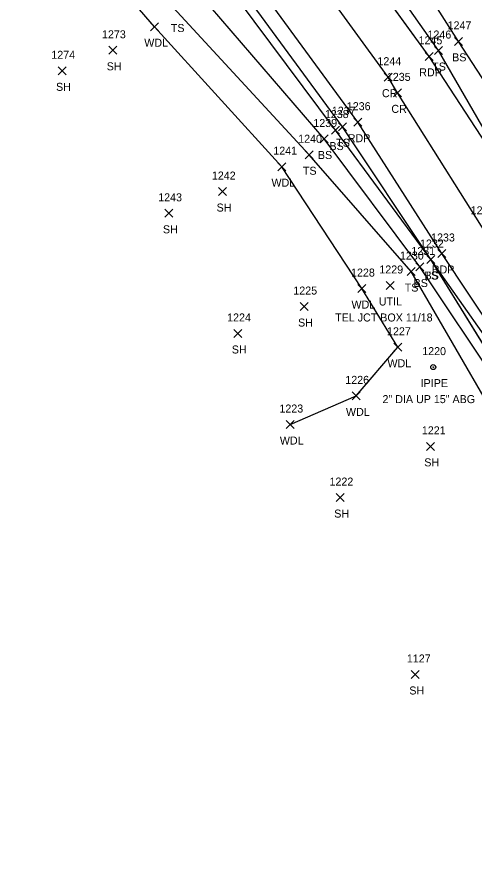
# Model space of a CAD drawing. Extents: x 1415642 to 1422021, y 544543 to 547232.
# Drawn here: x 1416332.5 to 1416447, y 546334.5 to 546547.3 of the extents above; entities that cross this region are included whole.
import ezdxf

# ---------------------------------------------------------------- set-up
doc = ezdxf.new("R2010")
doc.units = 0
for name, color, linetype in [('L_A', 7, 'Continuous'), ('L_I', 7, 'Continuous'), ('L_TIC', 7, 'Continuous'), ('LAWA', 7, 'Continuous'), ('LELB', 7, 'Continuous'), ('M_A', 7, 'Continuous'), ('M_C', 7, 'Continuous'), ('M_I', 7, 'Continuous'), ('MPIP', 7, 'Continuous'), ('P_A', 7, 'Continuous'), ('P_I', 7, 'Continuous'), ('P_TIC', 7, 'Continuous'), ('PET', 7, 'Continuous'), ('PRC', 7, 'Continuous'), ('U_A', 7, 'Continuous'), ('U_C', 7, 'Continuous'), ('U_I', 7, 'Continuous'), ('UDEFAULT', 7, 'Continuous')]:
    doc.layers.add(name, color=color, linetype=linetype)

msp = doc.modelspace()

# ---------------------------------------------------------------- linework, layer by layer
at = {"layer": 'L_TIC'}
for points in [[(1416365.86, 546543.85), (1416367.86, 546545.85)], [(1416367.86, 546543.85), (1416365.86, 546545.85)], [(1416441.83, 546540.19), (1416443.83, 546542.19)], [(1416443.83, 546540.19), (1416441.83, 546542.19)], [(1416355.4, 546537.95), (1416357.4, 546539.95)], [(1416357.4, 546537.95), (1416355.4, 546539.95)], [(1416436.87, 546537.89), (1416438.87, 546539.89)], [(1416438.87, 546537.89), (1416436.87, 546539.89)], [(1416342.74, 546532.82), (1416344.74, 546534.82)], [(1416344.74, 546532.82), (1416342.74, 546534.82)], [(1416412.88, 546518.84), (1416414.88, 546520.84)], [(1416414.88, 546518.84), (1416412.88, 546520.84)], [(1416411.14, 546518.01), (1416413.14, 546520.01)], [(1416413.14, 546518.01), (1416411.14, 546520.01)], [(1416408.26, 546515.78), (1416410.26, 546517.78)], [(1416410.26, 546515.78), (1416408.26, 546517.78)], [(1416404.55, 546511.84), (1416406.55, 546513.84)], [(1416406.55, 546511.84), (1416404.55, 546513.84)], [(1416397.67, 546508.86), (1416399.67, 546510.86)], [(1416399.67, 546508.86), (1416397.67, 546510.86)], [(1416382.88, 546502.64), (1416384.88, 546504.64)], [(1416384.88, 546502.64), (1416382.88, 546504.64)], [(1416369.46, 546497.2), (1416371.46, 546499.2)], [(1416371.46, 546497.2), (1416369.46, 546499.2)], [(1416434.93, 546485.65), (1416436.93, 546487.65)], [(1416436.93, 546485.65), (1416434.93, 546487.65)], [(1416434.93, 546485.65), (1416436.93, 546487.65)], [(1416436.93, 546485.65), (1416434.93, 546487.65)], [(1416430.01, 546482.64), (1416432.01, 546484.64)], [(1416432.01, 546482.64), (1416430.01, 546484.64)], [(1416432.2, 546483.78), (1416434.2, 546485.78)], [(1416434.2, 546483.78), (1416432.2, 546485.78)], [(1416417.68, 546478.39), (1416419.68, 546480.39)], [(1416419.68, 546478.39), (1416417.68, 546480.39)], [(1416403.25, 546473.89), (1416405.25, 546475.89)], [(1416405.25, 546473.89), (1416403.25, 546475.89)], [(1416386.69, 546467.16), (1416388.69, 546469.16)], [(1416388.69, 546467.16), (1416386.69, 546469.16)], [(1416426.69, 546463.71), (1416428.69, 546465.71)], [(1416428.69, 546463.71), (1416426.69, 546465.71)], [(1416416.31, 546451.56), (1416418.31, 546453.56)], [(1416418.31, 546451.56), (1416416.31, 546453.56)], [(1416399.77, 546444.4), (1416401.77, 546446.4)], [(1416401.77, 546444.4), (1416399.77, 546446.4)], [(1416434.83, 546438.94), (1416436.83, 546440.94)], [(1416436.83, 546438.94), (1416434.83, 546440.94)], [(1416412.3, 546426.14), (1416414.3, 546428.14)], [(1416414.3, 546426.14), (1416412.3, 546428.14)], [(1416431.07, 546381.91), (1416433.07, 546383.91)], [(1416433.07, 546381.91), (1416431.07, 546383.91)]]:
    msp.add_lwpolyline(points, dxfattribs=at)
at = {"layer": 'LAWA'}
for points in [[(1416400.77, 546445.4), (1416417.31, 546452.56), (1416427.69, 546464.71), (1416418.68, 546479.39), (1416398.67, 546509.86), (1416366.86, 546544.85), (1416337.81, 546578.41)], [(1416400.78, 546445.41), (1416417.3, 546452.56), (1416427.69, 546464.71), (1416418.68, 546479.4), (1416398.68, 546509.86), (1416366.86, 546544.85), (1416337.81, 546578.41)]]:
    msp.add_lwpolyline(points, dxfattribs=at)
at = {"layer": 'LELB'}
for points in [[(1416487.57, 546505.93), (1416480.71, 546505.12), (1416469.86, 546502.72), (1416462.76, 546510.55), (1416442.83, 546541.19), (1416430.44, 546560.72), (1416424.35, 546585.18), (1416398.34, 546624.28), (1416389.66, 546643.26), (1416377.3, 546653.03), (1416344.54, 546704.05), (1416343.42, 546724.77), (1416329.35, 546768.04), (1416303.68, 546799.52), (1416274.8, 546819.39), (1416239.26, 546839.41), (1416210.61, 546845.46), (1416203.47, 546849.21), (1416195, 546854.49)], [(1416487.57, 546505.93), (1416480.71, 546505.12), (1416469.86, 546502.72), (1416462.76, 546510.55), (1416442.83, 546541.19), (1416430.44, 546560.72), (1416424.35, 546585.18), (1416398.34, 546624.28), (1416389.66, 546643.27), (1416377.3, 546653.03), (1416344.54, 546704.05), (1416343.42, 546724.76), (1416329.35, 546768.04), (1416303.68, 546799.52), (1416274.8, 546819.4), (1416239.26, 546839.41), (1416210.61, 546845.46), (1416203.48, 546849.21), (1416195, 546854.49)], [(1416462.64, 546496.11), (1416437.87, 546538.89), (1416411.19, 546576.82), (1416382.17, 546614.17), (1416360.8, 546639.39), (1416323.65, 546683.15), (1416301.53, 546707.03), (1416273.6, 546735.69), (1416258.67, 546751.22), (1416224.41, 546784.74), (1416201.13, 546806.07), (1416169.09, 546832.26)], [(1416462.64, 546496.11), (1416437.87, 546538.89), (1416411.18, 546576.82), (1416382.17, 546614.17), (1416360.8, 546639.39), (1416323.65, 546683.15), (1416301.53, 546707.03), (1416273.6, 546735.69), (1416258.67, 546751.22), (1416224.4, 546784.74), (1416201.13, 546806.07), (1416169.09, 546832.26)], [(1416578, 546177.77), (1416578.55, 546199.27), (1416573.9, 546214.14), (1416552.43, 546269), (1416536.22, 546304.5), (1416520.22, 546335.71), (1416500.65, 546371.21), (1416484.25, 546405.14), (1416455.06, 546455.78), (1416435.93, 546486.65), (1416412.14, 546519.01), (1416383.64, 546557.13), (1416352.74, 546592.54), (1416331.82, 546618.14), (1416293.94, 546655.61), (1416274.22, 546680.91), (1416245.72, 546708.98), (1416224.27, 546729.93), (1416198.14, 546753.3), (1416170.94, 546765.48), (1416158.5, 546767.31), (1416141.08, 546772.75), (1416136.01, 546776.95), (1416129, 546780.64)], [(1416578, 546177.77), (1416578.55, 546199.27), (1416573.9, 546214.14), (1416552.42, 546269.01), (1416536.22, 546304.5), (1416520.22, 546335.71), (1416500.65, 546371.22), (1416484.25, 546405.15), (1416455.06, 546455.79), (1416435.93, 546486.65), (1416412.14, 546519.01), (1416383.65, 546557.13), (1416352.74, 546592.54), (1416331.82, 546618.14), (1416293.94, 546655.62), (1416274.22, 546680.91), (1416245.72, 546708.98), (1416224.27, 546729.93), (1416198.14, 546753.3), (1416170.94, 546765.48), (1416158.51, 546767.31), (1416141.09, 546772.75), (1416136.01, 546776.96), (1416129.01, 546780.64)], [(1416503.76, 546247.98), (1416498.74, 546274.69), (1416501.23, 546308.66), (1416502.98, 546324.04), (1416489.47, 546365.32), (1416480.57, 546403.46), (1416453.11, 546455.02), (1416433.2, 546484.78), (1416409.26, 546516.78), (1416378.25, 546552.92), (1416343.61, 546583.91), (1416327.57, 546614.09), (1416289.4, 546651.59), (1416267.58, 546675.69), (1416237.14, 546697.31), (1416220.66, 546725.9), (1416195.41, 546750.9), (1416170.78, 546763.33), (1416158.82, 546764.49), (1416140.16, 546770.72), (1416135.4, 546775.05), (1416128.27, 546778.63)], [(1416503.76, 546247.98), (1416498.74, 546274.69), (1416501.24, 546308.65), (1416502.98, 546324.03), (1416489.47, 546365.32), (1416480.57, 546403.46), (1416453.11, 546455.02), (1416433.2, 546484.78), (1416409.26, 546516.79), (1416378.25, 546552.92), (1416343.61, 546583.91), (1416327.58, 546614.09), (1416289.4, 546651.59), (1416267.58, 546675.69), (1416237.14, 546697.31), (1416220.66, 546725.9), (1416195.42, 546750.9), (1416170.78, 546763.33), (1416158.81, 546764.5), (1416140.16, 546770.72), (1416135.4, 546775.05), (1416128.28, 546778.62)], [(1416480.57, 546403.46), (1416449.3, 546452.17), (1416431.01, 546483.64), (1416405.55, 546512.84), (1416372.51, 546548.53), (1416341.49, 546581.99), (1416324.84, 546612.16), (1416286, 546648.13), (1416263.12, 546671.71)], [(1416480.57, 546403.46), (1416449.3, 546452.17), (1416431.01, 546483.64), (1416405.56, 546512.84), (1416372.51, 546548.53), (1416341.49, 546581.99), (1416324.84, 546612.16), (1416286, 546648.13), (1416263.12, 546671.71)], [(1416587.9, 546190.79), (1416583.62, 546199.97), (1416577.46, 546215.02), (1416552.43, 546269), (1416533.39, 546301.47), (1416525.26, 546316.84), (1416520.22, 546335.71), (1416504.13, 546372.91), (1416486.87, 546406.07), (1416456.87, 546456.96), (1416435.93, 546486.65), (1416413.88, 546519.84), (1416385.73, 546558.12)], [(1416587.91, 546190.79), (1416583.61, 546199.97), (1416577.46, 546215.02), (1416552.42, 546269.01), (1416533.39, 546301.47), (1416525.26, 546316.84), (1416520.22, 546335.71), (1416504.13, 546372.91), (1416486.87, 546406.07), (1416456.87, 546456.96), (1416435.93, 546486.65), (1416413.88, 546519.84), (1416385.73, 546558.12)]]:
    msp.add_lwpolyline(points, dxfattribs=at)
at = {"layer": 'MPIP'}
for radius in [0.625, 0.0833]:
    msp.add_circle((1416436.56, 546459.75), radius, dxfattribs=at)
at = {"layer": 'P_TIC'}
for points in [[(1416434.56, 546536.44), (1416436.56, 546538.44)], [(1416436.56, 546536.44), (1416434.56, 546538.44)], [(1416424.29, 546531.23), (1416426.29, 546533.23)], [(1416426.29, 546531.23), (1416424.29, 546533.23)], [(1416426.64, 546527.31), (1416428.64, 546529.31)], [(1416428.64, 546527.31), (1416426.64, 546529.31)], [(1416416.68, 546519.98), (1416418.68, 546521.98)], [(1416418.68, 546519.98), (1416416.68, 546521.98)], [(1416437.7, 546487.16), (1416439.7, 546489.16)], [(1416439.7, 546487.16), (1416437.7, 546489.16)]]:
    msp.add_lwpolyline(points, dxfattribs=at)
at = {"layer": 'PET'}
for points in [[(1416619.56, 546186.67), (1416601.63, 546226.16), (1416579.47, 546277.45), (1416562.03, 546315.23), (1416547.08, 546347.32), (1416527.73, 546384.04), (1416509.97, 546418.47), (1416487.43, 546457.37), (1416462.82, 546495.68), (1416435.56, 546537.44), (1416408.53, 546574.62)], [(1416619.56, 546186.67), (1416601.62, 546226.16), (1416579.47, 546277.45), (1416562.03, 546315.23), (1416547.08, 546347.32), (1416527.73, 546384.03), (1416509.97, 546418.46), (1416487.43, 546457.37), (1416462.82, 546495.68), (1416435.56, 546537.44), (1416408.53, 546574.61)], [(1416599.36, 546175.05), (1416589.42, 546196.6), (1416580.61, 546216.08), (1416556.35, 546269.48), (1416540.49, 546305), (1416525.46, 546337.37), (1416506.55, 546374.02), (1416489.16, 546406.45), (1416459.13, 546457.37), (1416438.7, 546488.16), (1416417.68, 546520.98), (1416388.9, 546560.28)], [(1416599.36, 546175.05), (1416589.42, 546196.6), (1416580.62, 546216.08), (1416556.34, 546269.48), (1416540.49, 546305), (1416525.46, 546337.38), (1416506.55, 546374.02), (1416489.16, 546406.45), (1416459.13, 546457.38), (1416438.7, 546488.17), (1416417.68, 546520.98), (1416388.9, 546560.28)]]:
    msp.add_lwpolyline(points, dxfattribs=at)
at = {"layer": 'PRC'}
for points in [[(1416610.25, 546183.67), (1416586.12, 546227.19), (1416567.64, 546274.51), (1416551.19, 546309.95), (1416536.28, 546342.88), (1416517.21, 546379.83), (1416500.09, 546412.89), (1416469.99, 546464.05), (1416448.59, 546494.95), (1416427.64, 546528.31), (1416425.29, 546532.23), (1416399.16, 546568.17)], [(1416610.26, 546183.67), (1416586.11, 546227.19), (1416567.64, 546274.51), (1416551.18, 546309.96), (1416536.27, 546342.88), (1416517.21, 546379.83), (1416500.09, 546412.89), (1416469.99, 546464.05), (1416448.59, 546494.95), (1416427.64, 546528.31), (1416425.29, 546532.24), (1416399.16, 546568.17)]]:
    msp.add_lwpolyline(points, dxfattribs=at)
at = {"layer": 'UDEFAULT'}
for points in [[(1416424.77, 546479.16), (1416426.77, 546481.16)], [(1416426.77, 546479.16), (1416424.77, 546481.16)]]:
    msp.add_lwpolyline(points, dxfattribs=at)

# ---------------------------------------------------------------- texts
at = {"layer": 'L_A'}
for s, p in [('TS', (1416370.92, 546543.53)), ('WDL', (1416364.28, 546539.85)), ('BS', (1416441.28, 546536.19)), ('SH', (1416354.89, 546533.95)), ('TS', (1416436.28, 546533.89)), ('SH', (1416342.22, 546528.82)), ('TS', (1416412.29, 546514.84)), ('BS', (1416410.59, 546514.01)), ('BS', (1416407.7, 546511.78)), ('TS', (1416403.96, 546507.84)), ('WDL', (1416396.09, 546504.86)), ('SH', (1416382.37, 546498.64)), ('SH', (1416368.95, 546493.2)), ('TS', (1416434.34, 546481.65)), ('BS', (1416434.37, 546481.65)), ('TS', (1416429.42, 546478.64)), ('BS', (1416431.64, 546479.78)), ('WDL', (1416416.1, 546474.39)), ('SH', (1416402.74, 546469.89)), ('SH', (1416386.18, 546463.16)), ('WDL', (1416425.1, 546459.71)), ('WDL', (1416414.72, 546447.56)), ('WDL', (1416398.19, 546440.4)), ('SH', (1416434.31, 546434.94)), ('SH', (1416411.79, 546422.14)), ('SH', (1416430.56, 546377.91))]:
    msp.add_text(s, height=2, dxfattribs=at).set_placement(p)
at = {"layer": 'L_I'}
for s, p in [('1247', (1416440.14, 546544.19)), ('1273', (1416353.71, 546541.95)), ('1246', (1416435.12, 546541.89)), ('1274', (1416341.04, 546536.82)), ('1237', (1416411.19, 546522.84)), ('1238', (1416409.45, 546522.01)), ('1239', (1416406.56, 546519.78)), ('1240', (1416402.77, 546515.84)), ('1241', (1416396.55, 546512.86)), ('1242', (1416381.19, 546506.64)), ('1243', (1416367.77, 546501.2)), ('1232', (1416433.24, 546489.65)), ('1232', (1416433.24, 546489.65)), ('1230', (1416428.23, 546486.64)), ('1231', (1416431.07, 546487.78)), ('1228', (1416415.99, 546482.39)), ('1225', (1416401.56, 546477.89)), ('1224', (1416385, 546471.16)), ('1227', (1416424.99, 546467.71)), ('1226', (1416414.56, 546455.56)), ('1223', (1416398.08, 546448.4)), ('1221', (1416433.7, 546442.94)), ('1222', (1416410.61, 546430.14)), ('1127', (1416429.95, 546385.91))]:
    msp.add_text(s, height=2, dxfattribs=at).set_placement(p)
at = {"layer": 'M_A'}
msp.add_text('IPIPE', height=2, dxfattribs=at).set_placement((1416433.4, 546454.75))
at = {"layer": 'M_C'}
msp.add_text('2" DIA UP 15" ABG', height=2, dxfattribs=at).set_placement((1416423.86, 546450.75))
at = {"layer": 'M_I'}
msp.add_text('1220', height=2, dxfattribs=at).set_placement((1416433.79, 546462.75))
at = {"layer": 'P_A'}
for s, p in [('RDP', (1416433.05, 546532.44)), ('CR', (1416423.72, 546527.23)), ('CR', (1416426.08, 546523.31)), ('RDP', (1416415.17, 546515.98)), ('RDP', (1416436.19, 546483.16))]:
    msp.add_text(s, height=2, dxfattribs=at).set_placement(p)
at = {"layer": 'P_I'}
for s, p in [('1245', (1416432.87, 546540.44)), ('1244', (1416422.59, 546535.23)), ('1235', (1416424.95, 546531.31)), ('1236', (1416414.93, 546523.98)), ('1234', (1416445.9, 546497.95)), ('1233', (1416436.01, 546491.16))]:
    msp.add_text(s, height=2, dxfattribs=at).set_placement(p)
at = {"layer": 'U_A'}
msp.add_text('UTIL', height=2, dxfattribs=at).set_placement((1416422.94, 546475.16))
at = {"layer": 'U_C'}
msp.add_text('TEL JCT BOX 11/18', height=2, dxfattribs=at).set_placement((1416412.01, 546471.16))
at = {"layer": 'U_I'}
msp.add_text('1229', height=2, dxfattribs=at).set_placement((1416423.07, 546483.16))

doc.saveas('drawing.dxf')
